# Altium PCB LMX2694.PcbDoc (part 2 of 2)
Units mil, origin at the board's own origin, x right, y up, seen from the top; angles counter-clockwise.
Board outline 2500 x 2200 mil, 4 copper layers (Top Layer, RF GND, Signal GND, Bottom Layer), stack 60.6 mil thick; 109 components, 60 nets, 306 pads, 206 vias.
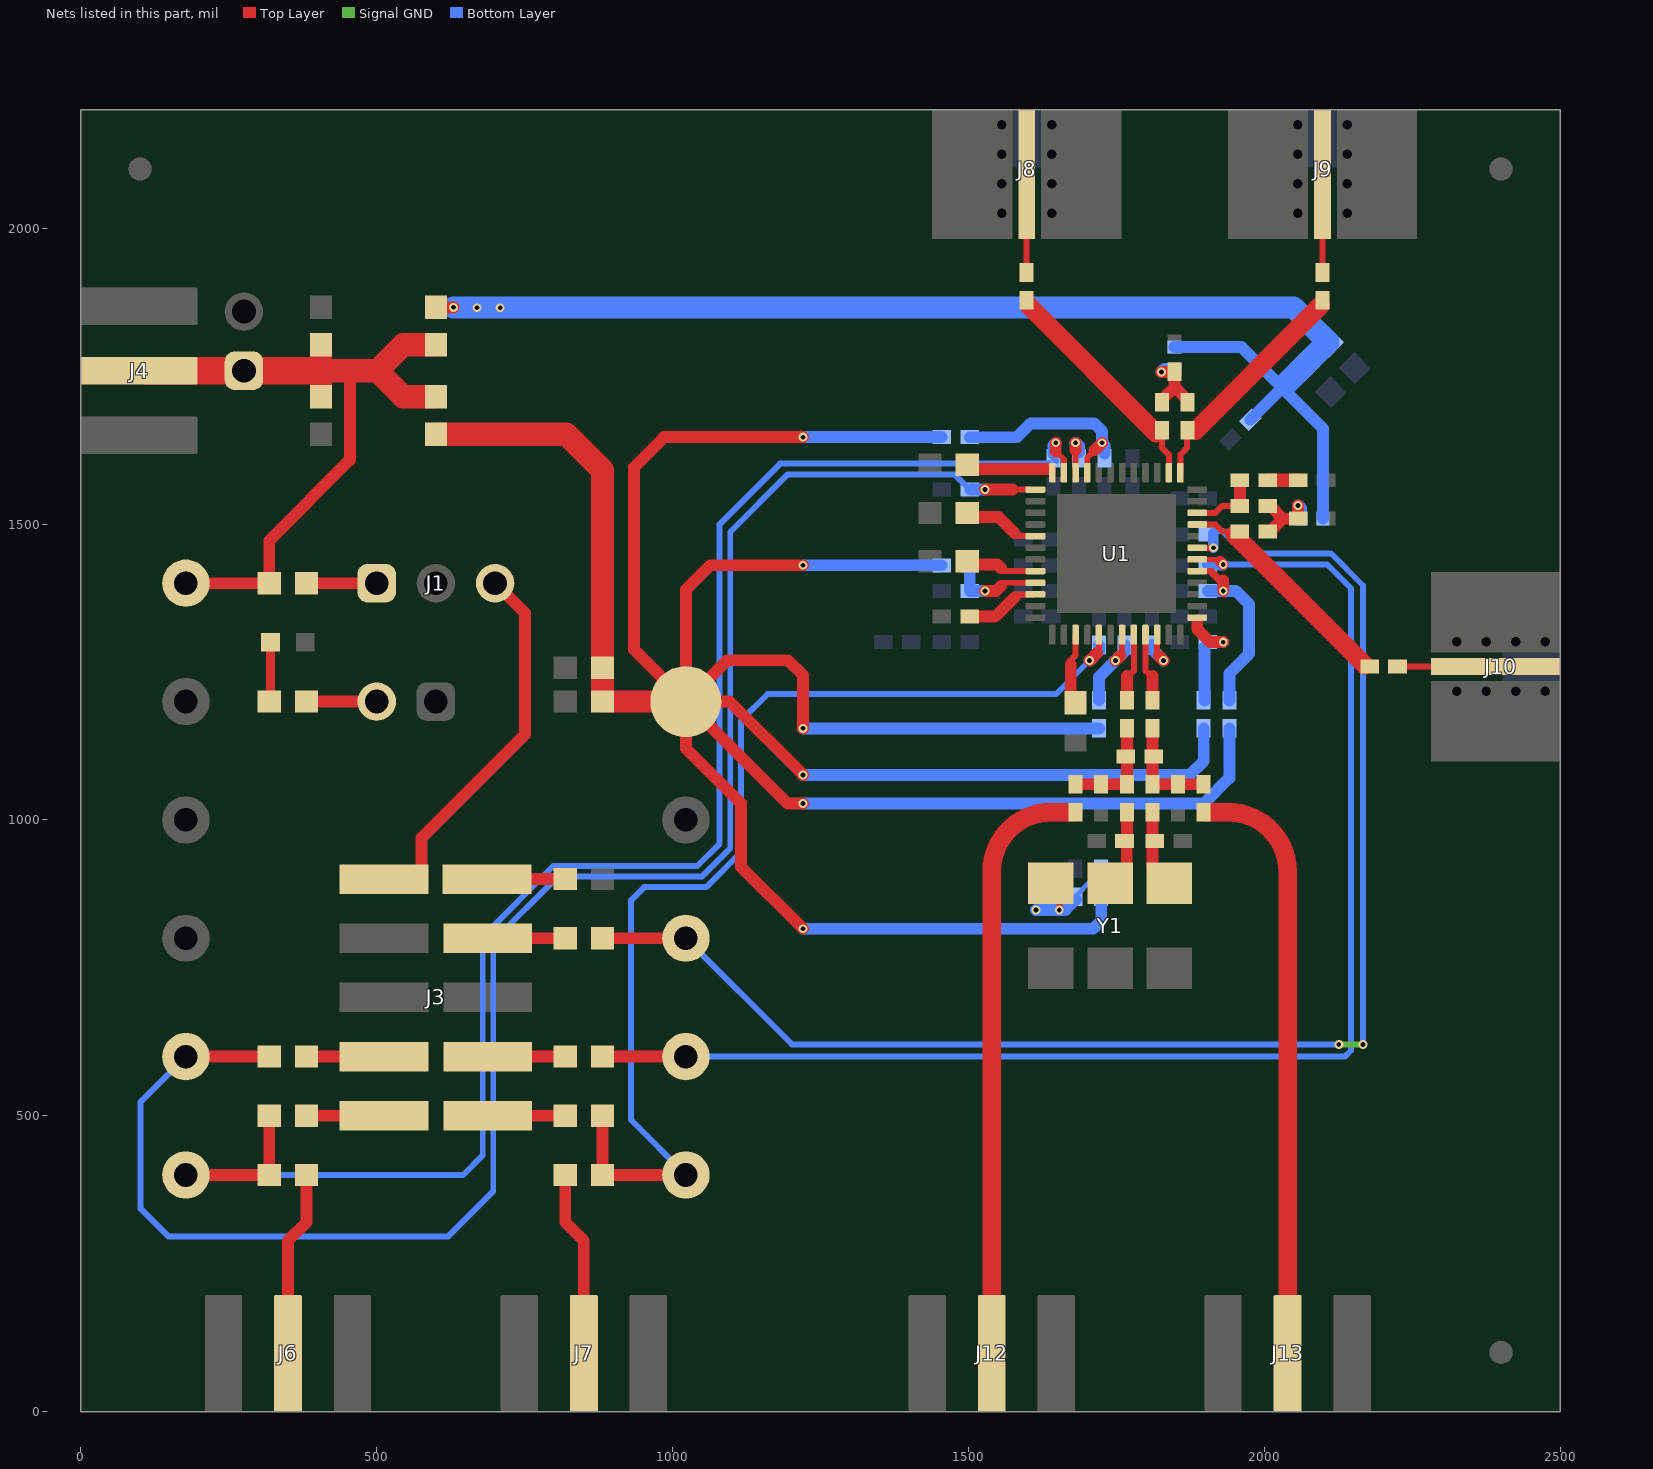
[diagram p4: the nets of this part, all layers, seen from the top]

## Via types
v1: diameter 15, hole 8, Top Layer to Bottom Layer, tented both sides, 181 vias
v2: diameter 19.68, hole 11.81, Top Layer to Bottom Layer, tented both sides, 25 vias

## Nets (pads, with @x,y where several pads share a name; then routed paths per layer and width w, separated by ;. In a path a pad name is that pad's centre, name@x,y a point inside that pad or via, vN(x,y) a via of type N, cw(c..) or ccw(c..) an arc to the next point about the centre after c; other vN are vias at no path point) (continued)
NetC14_1: C14.1 R18.2 U1.33 | length 357.2
  Top Layer w10: U1.33@1700.79,1585.83 U1.33@1700.79,1586.81 1700.79,1612.4 v1(1725.79,1637.4)
  Top Layer w20: 1713.19,1625 v1(1725.79,1637.4)
  Bottom Layer w20: R18.2@1502.36,1646.65 1581.89,1646.65 1605.32,1670.08 1712.2,1670.08 1725.79,1656.5 v1(1725.79,1637.4) 1730.12,1633.07 C14.1@1730.12,1619.49
NetC15_1: C15.1 R17.2 U1.45 | length 171.7
  Top Layer w10: 1550,1387.2 1556.89,1400 ; 1554.92,1400.79 U1.45@1613.19,1400.79 ; 1555.51,1395.67 1560.43,1399.61
  Top Layer w20: v1(1528.15,1387.01) 1545.87,1387.01 ; 1546.85,1387.01 1555.51,1395.67
  Bottom Layer w20: C15.1@1502.17,1387.01 v1@1528.35,1387.01 ; C15.1@1502.17,1393.9 R17.2@1502.17,1430.32
NetC16_1: C16.1 R16.2 U1.17 | length 329.7
  Top Layer w10: U1.17@1886.81,1420.13 U1.17@1886.81,1420.47 1909.25,1420.47
  Top Layer w12: 1910.43,1419.29 1930.71,1399.02 1934.45,1395.28
  Top Layer w20: v1(1930.71,1387.01) 1930.71,1399.02 1930.71,1404.53
  Bottom Layer w20: C16.1@1904.53,1387.01 v1(1930.71,1387.01) 1951.57,1387.01 1974.41,1364.17 1974.41,1280.71 1940.94,1247.24 R16.2@1940.94,1201.97
NetC17_1: C17.1 R15.2 U1.13 | length 183.6
  Top Layer w20: U1.13@1886.81,1337.01 1886.81,1322.05 1908.46,1300.39 v1(1930.71,1300.39)
  Bottom Layer w20: R15.2@1899.02,1201.97 C17.1@1899.02,1291.73 ; C17.1@1904.72,1300.39 v1(1930.71,1300.39)
NetC18_1: C18.1 R14.2 U1.7 | length 155.1
  Top Layer w10: 1759.84,1280.51 U1.7@1759.84,1313.19
  Top Layer w20: v1@1748.43,1269.09 1756.3,1276.97
  Bottom Layer w20: R14.2@1720.47,1202.17 1720.47,1241.34 v1(1748.43,1269.29) 1763.78,1284.65 C18.1@1763.78,1295.47
NetC19_1: C19.1 U1.10 | length 78
  Top Layer w10: 1818.9,1280.12 U1.10@1818.9,1313.19
  Top Layer w20: 1822.24,1276.77 v1(1829.72,1269.29)
  Bottom Layer w20: C19.1@1810.04,1295.47 1810.04,1288.98 v1(1829.72,1269.29)
NetC20_1: C20.1 U1.46 | length 113
  Top Layer w10: 1576.57,1381.1 U1.46@1611.02,1381.1
  Top Layer w20: C20.1@1510.83,1343.9 1544.09,1343.9 ; 1546.06,1344.09 1578.15,1375.98
NetC21_1: C21.1 U1.44 | length 114.2
  Top Layer w10: 1554.72,1420.47 U1.44@1613.19,1420.47
  Top Layer w20: C21.1@1502.17,1432.87 1503.35,1431.69 1548.82,1431.69 1554.92,1425.59
NetC22_1: C22.1 U1.36 | length 139.6
  Top Layer w10: C22.1@1509.06,1598.23 C22.1@1509.25,1598.43 ; U1.36@1641.73,1586.81 U1.36@1641.73,1598.43
  Top Layer w20: C22.1@1509.25,1592.91 U1.36@1637.01,1592.91
NetC23_1: C23.1 U1.3 | length 107.8
  Top Layer w10: 1670.47,1267.72 1681.1,1278.35 U1.3@1681.1,1313.19 ; C23.1@1671.26,1205.71 C23.1@1672.05,1206.5 ; C23.1@1680.91,1198.43 C23.1@1681.1,1198.62
  Top Layer w20: C23.1@1672.83,1206.5 1672.83,1262.99
NetC24_1: C24.1 U1.34 | length 70.1
  Top Layer w10: U1.34@1681.1,1586.81 1681.1,1625.59
  Top Layer w20: 1681.1,1625.39 v1(1681.1,1637.4)
  Bottom Layer w20: v1(1681.1,1637.4) 1686.81,1631.69 C24.1@1686.81,1620.47
NetC25_1: C25.1 U1.41 | length 136.6
  Top Layer w10: 1573.23,1489.96 1583.66,1479.53 ; 1579.13,1479.53 U1.41@1613.39,1479.53
  Top Layer w20: C25.1@1502.56,1511.02 1503.54,1512.01 1550.59,1512.01 1578.35,1484.45
NetC26_2: C26.2 L1.2 R19.2 R20.2 | length 141.7
  Top Layer w10: R19.2@1826.77,1705.91 R19.2@1826.77,1709.84 ; R20.2@1869.88,1705.91 R20.2@1869.88,1710.04
  Top Layer w15: C26.2@1848.43,1757.09 C26.2@1848.82,1757.09
  Top Layer w20: v1(1826.18,1757.09) C26.2@1848.43,1757.09 1848.43,1731.5 ; R19.2@1826.77,1709.84 1848.43,1731.5 ; R20.2@1869.88,1710.04 1848.43,1731.5
  Bottom Layer w10: L1.2@1848.43,1762.01 L1.2@1848.62,1762.01
  Bottom Layer w20: v1(1826.18,1757.09) 1831.1,1762.01 L1.2@1848.43,1762.01
NetC27_1: C27.1 J8.1 | length 169.7
  Top Layer w10: C27.1@1598.43,1925.2 J8.1@1598.43,2091 J8.1@1598.43,2094.88
NetC27_2: C27.2 R19.1 U1.26 | length 381.9
  Top Layer w10: R19.1@1826.77,1658.66 1826.77,1629.13 1838.58,1617.32 U1.26@1838.58,1586.81
  Top Layer w31.5: C27.2@1601.77,1869.29 R19.1@1817.52,1653.54
NetC28_1: C28.1 J9.1 | length 171.2
  Top Layer w10: J9.1@2097.64,2096.06 2098.43,2095.28 J9.1@2098.43,2091 C28.1@2098.43,1925.2
NetC28_2: C28.2 R20.1 U1.25 | length 376
  Top Layer w10: U1.25@1858.27,1586.81 1858.27,1617.32 1869.68,1628.74 R20.1@1869.68,1658.66
  Top Layer w31.5: 1883.66,1657.87 C28.2@2095.47,1869.49
NetC29_2: C29.2 L2.2 R21.2 R22.2 | length 141.2
  Top Layer w10: R22.2@2005.91,1487.4 R22.2@2009.84,1487.4 ; R21.2@2005.91,1530.71 R21.2@2009.84,1530.71
  Top Layer w20: R22.2@2009.84,1487.4 2031.5,1509.06 ; R21.2@2009.84,1530.71 2031.5,1509.06 ; v1(2057.09,1531.3) C29.2@2057.09,1509.06 2031.5,1509.06
  Bottom Layer w20: v1(2057.09,1531.3) 2062.01,1526.38 L2.2@2062.01,1509.06
NetC30_1: C30.1 R33.2 | length 52.5
  Top Layer w12: C30.1@2004.92,1573.23 2005.71,1574.02 C30.1@2005.91,1574.02
  Top Layer w23.62: C30.1@2005.91,1574.02 R33.2@2057.09,1574.02
NetC30_2: C30.2 R21.1 U1.22 | length 120.9
  Top Layer w10: U1.22@1886.81,1518.9 1917.32,1518.9 1929.13,1530.71 R21.1@1958.66,1530.71
  Top Layer w10.24: R21.1@1958.66,1530.71 1958.66,1530.12 R21.1@1958.86,1529.92
  Top Layer w20: R21.1@1958.66,1530.71 C30.2@1958.66,1574.02
NetC31_1: C31.1 J10.1 | length 165.8
  Top Layer w10.24: C31.1@2225.2,1259.06 J10.1@2391,1259.06
NetC31_2: C31.2 R22.1 U1.21 | length 387.4
  Top Layer w10: U1.21@1886.81,1499.21 1917.32,1499.21 1929.13,1487.4 R22.1@1958.66,1487.4
  Top Layer w31.5: R22.1@1950.2,1481.5 C31.2@2169.88,1261.81
NetC32_1: C32.1 U1.8 | length 119.3
  Top Layer w10: 1767.52,1240.16 1767.72,1240.16 1779.53,1251.97 U1.8@1779.53,1313.19
  Top Layer w20: C32.1@1767.72,1201.97 1767.72,1243.11
NetC32_2: C32.2 R23.2 R25.2 R29.2 R31.1 | length 165.9
  Top Layer w20: R31.1@1681.1,1060.24 1723.62,1060.24 R29.2@1724.41,1060.24 R25.2@1767.72,1060.24 R23.2@1767.72,1100.59 ; R23.2@1767.72,1115.75 C32.2@1767.72,1154.72
NetC33_1: C33.1 U1.9 | length 121.9
  Top Layer w10: U1.9@1799.21,1313.19 1799.21,1251.97 1811.61,1239.57 1811.61,1237.6
  Top Layer w20: C33.1@1811.02,1201.97 1811.02,1243.11
NetC33_2: C33.2 R23.1 R28.1 R30.2 R32.1 | length 153.9
  Top Layer w20: R23.1@1811.02,1097.83 R28.1@1811.02,1060.24 R30.2@1854.33,1060.24 ; R23.1@1811.02,1115.94 C33.2@1811.02,1154.72 ; R30.2@1863.39,1060.24 R32.1@1897.64,1060.24
NetC34_1: C34.1 R24.2 Y1.6 | length 185.6
  Top Layer w10: v1(1653.54,847.83) 1653.54,892.13 Y1.6@1654.72,893.31
  Bottom Layer w8: C34.1@1681.1,870.08 R24.2@1724.41,917.32
  Bottom Layer w10: v1@1653.35,847.83 v1@1653.94,848.43
  Bottom Layer w20: v1(1614.17,847.83) v1@1653.35,847.83 ; v1(1653.54,847.83) 1663.78,847.83 C34.1@1681.69,865.75
NetD1_1: D1.1 R8.2 | length 100.4
  Top Layer w15: R8.2@319.09,1200.2 320.47,1201.57 D1.1@320.47,1300
NetJ1_1: J1.1 R7.1 | length 119.2
  Top Layer w20: R7.1@381.5,1401.57 383.07,1400 J1.1@500,1400
NetJ1_3: J1.3 J3.1 | length 596
  Top Layer w20: J3.1@575.59,897.44 575.59,969.29 750.39,1144.09 750.39,1349.8 J1.3@700,1400.2
NetJ2_2: J2.2 R8.1 | length 117.7
  Top Layer w20: R8.1@382.28,1200 J2.2@500,1200
NetJ3_2: J3.2 R6.1 | length 133.5
  Top Layer w10: R6.1@818.5,900 R6.1@820,900
  Top Layer w20: J3.2@686.5,900 R6.1@818.5,900
NetJ3_4: J3.4 R5.1 | length 132.5
  Top Layer w10: R5.1@818.5,800 R5.1@820,800
  Top Layer w20: J3.4@687.5,800 R5.1@818.5,800
NetJ3_7: J3.7 R1.2 | length 127.5
  Top Layer w20: R1.2@385,600 J3.7@512.5,600
NetJ3_8: J3.8 R4.1 | length 134.6
  Top Layer w10: R4.1@815,600 R4.1@820,595
  Top Layer w20: J3.8@687.5,600 R4.1@815,600
NetJ3_9: J3.9 R2.1 | length 128.5
  Top Layer w20: R2.1@381.5,500 J3.9@510,500
NetJ3_10: J3.10 R3.1 | length 132.5
  Top Layer w10: R3.1@818.5,500 R3.1@820,500
  Top Layer w20: J3.10@687.5,500 R3.1@818.5,500
NetJ6_1: J6.1 R11.1 | length 319.7
  Top Layer w20: J6.1@350,93.31 J6.1@350,98.33 350,288.58 381.5,320.08 R11.1@381.5,400
NetJ7_1: J7.1 R12.1 | length 321.7
  Top Layer w20: R12.1@818.5,400 818.5,320.08 850,288.58 J7.1@850,98.33 850,94.09 J7.1@848.03,92.13
NetJ12_1: J12.1 R31.2 | length 999.6
  Top Layer w10: J12.1@1539.37,107.87 J12.1@1539.37,110
  Top Layer w31.5: J12.1@1539.37,110 1539.37,912.99 cw(c1639.37,912.99) 1639.37,1012.99 R31.2@1676.77,1012.99
NetJ13_1: J13.1 R32.2 | length 998
  Top Layer w10: J13.1@2039.37,109.45 J13.1@2039.37,110
  Top Layer w31.5: R32.2@1901.97,1012.99 1939.37,1012.99 cw(c1939.37,912.99) 2039.37,912.99 J13.1@2039.37,110
NetR25_1: R25.1 R26.1 Y1.5 | length 97.2
  Top Layer w20: Y1.5@1737.4,893.31 Y1.5@1739.37,893.31 ; R26.1@1763.78,964.57 1767.52,960.83 Y1.5@1767.52,919.29 ; R26.1@1767.72,964.57 R25.1@1767.72,1012.99
NetR27_1: R27.1 R28.2 Y1.4 | length 87.9
  Top Layer w20: R27.1@1810.83,971.85 1811.02,972.05 R28.2@1811.02,1012.99 ; Y1.4@1811.02,919.49 1811.02,960.63 R27.1@1814.96,964.57
RECAL_EN: C1.1 R1.1 TP5.1 U1.37 | length 3053.6
  Top Layer w10: 1574.8,1558.27 U1.37@1604.33,1558.27
  Top Layer w20: TP5.1@180,600 R1.1@318.5,600 ; v1(1528.15,1558.27) 1574.8,1558.27
  Bottom Layer w10: TP5.1@177.5,600 100.55,523.05 100.55,343.62 147.95,296.22 620.83,296.22 697.01,372.4 697.01,795.35 805.83,904.17 1049.25,904.17 1097.44,952.36 1097.44,1486.61 1194.88,1584.06 1476.18,1584.06 C1.1@1501.97,1558.27
  Bottom Layer w20: C1.1@1503.35,1558.27 v1(1528.15,1558.27)
SCK: C4.1 R4.2 TP8.1 U1.18 | length 2342.1
  Top Layer w8: U1.18@1886.81,1440.16 1922.05,1440.16 ; v1@1930.73,1432.66 v1@1930.91,1432.48
  Top Layer w18: 1924.8,1437.4 v1(1930.71,1431.5)
  Top Layer w20: R4.2@881.5,600 TP8.1@1020,600
  Bottom Layer w10: TP8.1@1022.44,600 TP8.1@1022.5,600 ; TP8.1@1030,600 2136.02,600 2146.46,610.43 2146.46,1391.34 2106.3,1431.5 v1(1930.71,1431.5)
  Bottom Layer w20: C4.1@1905.12,1431.5 v1(1930.71,1431.5)
SDI: C5.1 R5.2 TP4.1 U1.19 | length 2475.2
  Top Layer w10: U1.19@1886.81,1459.84 v1@1912.8,1459.84
  Top Layer w20: R5.2@881.5,800 TP4.1@1020,800
  Signal GND w10: v1(2125.98,620.47) v1(2166.93,620.47)
  Bottom Layer w10: TP4.1@1022.5,800 1202.03,620.47 v1(2125.98,620.47) ; C5.1@1913.39,1488.58 1929.13,1488.58 1967.36,1450.35 2112.72,1450.35 2166.93,1396.14 v1(2166.93,620.47)
  Bottom Layer w18: v1(1913.98,1459.84) C5.1@1913.98,1484.25
SYNC: C3.1 R3.2 R12.2 TP7.1 U1.5 | length 1901.2
  Top Layer w10: R12.2@880,400 R12.2@881.5,401.5 ; TP7.1@1020,400 TP7.1@1025,395 ; 1720.47,1285.04 U1.5@1720.47,1313.19
  Top Layer w20: R12.2@881.5,400 TP7.1@1020,400 ; R12.2@881.5,401.5 R3.2@881.5,500 ; v1(1704.72,1269.29) 1717.52,1282.09
  Bottom Layer w10: TP7.1@1023.03,399.61 929.92,492.72 929.92,864.37 951.85,886.3 1056.66,886.3 1115.31,944.96 1115.31,1167.48 1160.43,1212.6 1648.03,1212.6 v1(1704.72,1269.29)
  Bottom Layer w20: v1(1704.72,1269.29) 1720.47,1285.04 C3.1@1720.47,1295.28
SYSREFREQ: C2.1 R2.2 R11.2 TP6.1 U1.35 | length 2813.5
  Top Layer w10: R11.2@318.5,401.5 R11.2@320,400 ; 1647.44,1623.03 1647.64,1622.83 1661.42,1609.06 U1.35@1661.42,1586.81
  Top Layer w20: TP6.1@180,400 R11.2@318.5,400 ; R11.2@318.5,401.5 R2.2@318.5,500 ; 1647.64,1622.05 1647.64,1622.83 v1(1647.64,1637.4)
  Bottom Layer w10: TP6.1@177.5,400 646.06,400 679.13,433.07 679.13,802.76 798.43,922.05 1041.73,922.05 1079.57,959.88 1079.57,1499.65 1181.89,1601.97 C2.1@1636.81,1601.97 ; C2.1@1643.5,1611.22 1647.83,1606.89 C2.1@1647.83,1606.1
  Bottom Layer w20: C2.1@1643.5,1618.9 1643.5,1633.27 v1(1647.64,1637.4)
VCC: C9.1 C10.1 pad.1 R9.2 R14.1 R15.1 R16.1 R17.1 R18.1 R24.1 | length 6366.8
  Top Layer w20: v1(1220.47,816.14) 1115.55,921.06 1115.55,1027.95 1022.5,1121 pad.1@1022.5,1200 ; v1(1220.47,1027.56) 1194.94,1027.56 pad.1@1022.5,1200 ; v1(1220.47,1075.98) 1096.46,1200 pad.1@1022.5,1200 ; v1(1220.47,1154.72) 1220.47,1244.09 1194.88,1269.68 1092.18,1269.68 pad.1@1022.5,1200 ; v1(1220.47,1430.32) 1063.58,1430.32 1022.5,1389.23 pad.1@1022.5,1200 ; v1(1220.47,1646.85) 985.63,1646.85 934.84,1596.06 934.84,1287.66 pad.1@1022.5,1200
  Top Layer w37.4: C9.1@881.89,1200 pad.1@1022.5,1200
  Top Layer w39.37: R9.2@602.36,1651.97 820.67,1651.97 881.5,1591.14 C10.1@881.5,1257.09 C9.1@881.5,1206.69
  Bottom Layer w20: v1(1220.47,816.14) 1710.83,816.14 1724.41,829.72 R24.1@1724.41,870.08 ; v1(1220.47,1027.56) 1897.44,1027.56 1940.94,1071.06 R16.1@1940.94,1154.72 ; v1(1220.47,1075.98) 1874.21,1075.98 1897.64,1099.41 R15.1@1897.64,1154.72 ; v1(1220.47,1154.72) R14.1@1720.47,1154.72 ; v1(1220.47,1430.32) R17.1@1454.72,1430.32 ; v1(1220.47,1646.85) R18.1@1454.72,1646.85
VCCRF: C11.1 C12.1 L1.1 L2.1 R10.2 R13.1 | length 2169.7
  Top Layer w20: R10.2@600,1866.14 v1(629.92,1866.14)
  Bottom Layer w20: L1.1@1848.43,1799.41 1961.42,1799.41 2030.41,1730.41 ; R13.1@1976.35,1676.35 2030.41,1730.41 ; C11.1@2067.52,1767.52 2067.72,1767.72 C11.1@2067.91,1767.72 ; L2.1@2099.41,1509.06 2099.41,1661.42 2030.41,1730.41
  Bottom Layer w37.4: v1(629.92,1866.14) 2049.61,1866.14 C12.1@2107.87,1807.87
  Bottom Layer w39.37: 2036.02,1736.02 C11.1@2067.52,1767.52 ; C11.1@2067.72,1767.72 C12.1@2107.09,1807.09
  other v1: 669.29,1865.55 708.66,1865.55
VDD: C7.1 C8.1 J4.1 J5.1 R7.2 R9.1 R10.1 TP10.1 | length 1268.6
  Top Layer w20: TP10.1@177.5,1400 R7.2@317.91,1400 ; R7.2@318.5,1399.02 318.5,1472.05 454.72,1608.27 454.72,1758.86 ; C8.1@404.33,1803.74 C8.1@405.71,1802.36
  Top Layer w37.4: C7.1@405.71,1714.96 405.71,1759.06 C8.1@405.71,1802.36
  Top Layer w39.37: 405.71,1759.06 500.79,1759.06 ; R9.1@598.43,1714.96 544.88,1714.96 500.79,1759.06 ; R10.1@598.43,1803.15 544.88,1803.15 500.79,1759.06
  Top Layer w47.24: J4.1@110.04,1759.06 J5.1@275.59,1759.06 405.71,1759.06
pads on no net: FID1.1 FID2.1 FID3.1 FID4.1 FID5.1 FID6.1 J3.5 SH-J1.0 SH-J2.0 U1.11 U1.12 U1.20 U1.30 U1.31 U1.38 U1.39 Y1.1 Y1.2

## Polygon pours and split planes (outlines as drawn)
GND on Top Layer "TOP_LAYER_GND_P018" (solid, remove dead copper, pour order 18): 25,1978.74 25,1884.25 196.85,1884.25 196.85,1978.74
NetC30_2 on Top Layer "TOP_LAYER_NETC30_2_P022" (solid, pour order 22): 1912.99,1521.65 1933.86,1542.52 1964.17,1542.52 1964.17,1518.9 1912.99,1518.9
NetC31_2 on Top Layer "TOP_LAYER_NETC31_2_P032" (solid, pour order 32): 1942.13,1467.32 1961.81,1467.32 1961.81,1499.21 1910.24,1499.21
NetC31_1 on Top Layer "TOP_LAYER_NETC31_1_P038" (solid, remove dead copper, pour order 38): 2287.4,1273.23 2209.45,1273.23 2209.45,1244.88 2287.4,1244.88
no net on Top Layer "TOP_LAYER_NONET_P054" (solid, remove dead copper, pour order 54): 2193.7,1273.23
NetC31_2 on Top Layer "TOP_LAYER_NETC31_2_P056" (solid, remove dead copper, pour order 56): 2157.48,1251.97 2157.48,1273.23 2193.7,1273.23 2193.7,1244.88 2164.57,1244.88
NetC28_2 on Top Layer "TOP_LAYER_NETC28_2_P058" (solid, remove dead copper, pour order 58): 1870.87,1622.83 1896.46,1648.43 1858.27,1648.43 1858.27,1622.83
NetC28_1 on Top Layer "TOP_LAYER_NETC28_1_P060" (solid, remove dead copper, pour order 60): 2084.25,1984.25 2084.25,1909.45 2112.6,1909.45 2112.6,1984.25
NetC28_2 on Top Layer "TOP_LAYER_NETC28_2_P062" (solid, remove dead copper, pour order 62): 2112.6,1893.7 2112.6,1864.57 2105.51,1857.48 2090.55,1857.48 2075.89,1872.15 2084.25,1880.51 2084.25,1893.7
NetC27_1 on Top Layer "TOP_LAYER_NETC27_1_P064" (solid, remove dead copper, pour order 64): 1584.25,1984.25 1584.25,1909.45 1612.6,1909.45 1612.6,1984.25
NetC27_2 on Top Layer "TOP_LAYER_NETC27_2_P066" (solid, remove dead copper, pour order 66): 1827.17,1621.65 1796.85,1651.97 1796.85,1656.69 1797.05,1656.89 1838.58,1656.89 1838.58,1621.65
NetC27_2 on Top Layer "TOP_LAYER_NETC27_2_P068" (solid, remove dead copper, pour order 68): 1584.25,1893.7 1584.25,1864.57 1601.57,1847.24 1601.57,1873.43 1611.61,1873.43 1612.6,1872.44 1612.6,1893.7
no net on Top Layer "TOP_LAYER_NONET_P072" (solid, remove dead copper, pour order 72): 1813.58,1249.61
no net on Top Layer "TOP_LAYER_NONET_P076" (solid, remove dead copper, pour order 76): 1600.79,625.98
no net on Top Layer "TOP_LAYER_NONET_P080" (solid, remove dead copper, pour order 80): 2183.86,1683.27
GND on Top Layer "TOP_LAYER_GND_P084" (solid, remove dead copper, pour order 84): 1875.98,716.14 1877.95,716.14 1877.95,693.9 1800.79,693.9 1800.79,716.14
GND on Top Layer "TOP_LAYER_GND_P102" (solid, remove dead copper, pour order 102): 2283.46,1234.65 2209.45,1234.65 2209.45,1195.28 2283.46,1195.28
GND on Top Layer "TOP_LAYER_GND_P108" (solid, remove dead copper, pour order 108): 1622.83,1987.2 1622.83,1909.45 1637.99,1909.45 1662.2,1933.66 1662.2,1987.2
GND on Top Layer "TOP_LAYER_GND_P112" (solid, remove dead copper, pour order 112): 1534.65,1983.46 1534.65,1909.45 1574.02,1909.45 1574.02,1983.46
GND on Top Layer "TOP_LAYER_GND_P114" (solid, remove dead copper, pour order 114): 2122.83,1983.46 2122.83,1909.45 2162.2,1909.45 2162.2,1983.46
GND on Top Layer "TOP_LAYER_GND_P116" (solid, remove dead copper, pour order 116): 2284.65,1283.46 2209.45,1283.46 2209.45,1298.62 2233.66,1322.83 2284.65,1322.83
GND on Top Layer "TOP_LAYER_GND_P118" (solid, remove dead copper, pour order 118): 2073.62,1984.65 2073.62,1909.45 2058.46,1909.45 2034.25,1933.66 2034.25,1984.65
NetC4LF_1 on Top Layer "TOP_LAYER_NETC4LF_1_P120" (solid, remove dead copper, pour order 120): 1585.24,1452.17 1594.29,1443.11 1585.24,1443.11
NetC25_1 on Top Layer "TOP_LAYER_NETC25_1_P122" (solid, remove dead copper, pour order 122): 1584.65,1491.93 1593.7,1482.87 1584.65,1482.87
NetC21_1 on Top Layer "TOP_LAYER_NETC21_1_P124" (solid, remove dead copper, pour order 124): 1561.49,1433 1570.55,1423.94 1561.49,1423.94
NetC32_1 on Top Layer "TOP_LAYER_NETC32_1_P134" (solid, remove dead copper, pour order 134): 1760.83,1250.2 1776.97,1266.34 1777.36,1266.34 1777.36,1250.2
NetC33_1 on Top Layer "TOP_LAYER_NETC33_1_P136" (solid, remove dead copper, pour order 136): 1818.11,1250 1803.54,1264.57 1802.76,1264.57 1802.76,1250
GND on Top Layer "TOP_LAYER_GND_P140" (solid, remove dead copper, pour order 140): 196.85,1633.86 25,1633.86 25,1539.37 196.85,1539.37
VCCRF on Top Layer "TOP_LAYER_VCCRF_P142" (solid, remove dead copper, pour order 142): 617.72,1885.83 724.41,1885.83 724.41,1846.46 617.72,1846.46
NetC15_1 on Top Layer "TOP_LAYER_NETC15_1_P144" (solid, remove dead copper, pour order 144): 1561.81,1387.99 1570.87,1397.05 1570.87,1397.44 1561.81,1397.44
NetC20_1 on Top Layer "TOP_LAYER_NETC20_1_P146" (solid, remove dead copper, pour order 146): 1580.32,1364.27 1580.51,1364.27 1594.88,1378.64 1580.32,1378.64
NetC23_1 on Top Layer "TOP_LAYER_NETC23_1_P150" (solid, remove dead copper, pour order 150): 1682.68,1262.99 1682.68,1275.59 1676.77,1275.59 1675.98,1274.8 1675.98,1262.99
NetC34_1 on Top Layer "TOP_LAYER_NETC34_1_P152" (solid, remove dead copper, pour order 152): 1600.79,859.06 1600.79,837.99 1677.95,837.99 1677.95,859.06
GND on Top Layer "TOP_LAYER_GND_P161" (solid, pour order 161): 130.32,25 217.72,25 217.72,196.85 130.32,196.85
GND on Top Layer "TOP_LAYER_GND_P163" (solid, pour order 163): 483.46,25 569.68,25 569.68,196.85 483.46,196.85
GND on Top Layer "TOP_LAYER_GND_P165" (solid, pour order 165): 630.32,25 717.32,25 717.32,196.85 630.32,196.85
GND on Top Layer "TOP_LAYER_GND_P167" (solid, pour order 167): 983.46,25 1069.68,25 1069.68,196.85 983.46,196.85
NetC30_2 on Top Layer "TOP_LAYER_NETC30_2_P169" (solid, remove dead copper, pour order 169): 1942.91,1564.37 1942.91,1540.55 1974.41,1540.55 1974.41,1564.37
no net on Bottom Layer "BOTTOM_LAYER_NONET_P086" (solid, remove dead copper, pour order 86): 1876.97,1576.18
NetC13_1 on Bottom Layer "BOTTOM_LAYER_NETC13_1_P088" (solid, pour order 88): 1887.99,1553.94 1876.97,1564.96 1876.97,1578.15 1896.65,1578.15 1896.65,1565.55 1908.27,1553.94
SDI on Bottom Layer "BOTTOM_LAYER_SDI_P090" (solid, pour order 90): 1920.28,1471.06 1921.46,1469.88 1921.46,1459.84 1906.5,1459.84 1906.5,1471.06
GND on Bottom Layer "BOTTOM_LAYER_GND_P154" (solid, remove dead copper, pour order 154): 0.28,2200 2500.28,2200 2500.28,0 0.28,0
GND on Signal GND "SIGNAL_GND_GND_P156" (solid, remove dead copper, pour order 156): 0,2200 2500,2200 2500,0 0,0
no net on Top Overlay "NONET_L-01_P-001" (solid): 1596.46,1296.46 1612.2,1296.46 1596.46,1312.2
NetC27_2 on Top Solder "NONET_L-01_P-001" (solid): 1616.34,1877.76 1616.34,1856.3 1591.54,1856.3 1809.05,1638.78 1809.05,1685.04
no net on Top Solder "NONET_L-01_P-001" (solid): 2080.71,1877.95 2080.71,1856.3 2105.32,1856.3 1887.8,1638.78 1887.8,1685.04
no net on Top Solder "NONET_L-01_P-001" (solid, remove dead copper): 2079.72,1753.94
no net on Top Solder "NONET_L-01_P-001" (solid): 1883.86,1636.81 1857.28,1636.81 1857.28,1624.02 1852.36,1619.09 1852.36,1611.42 1864.17,1611.42 1864.17,1615.16 1883.86,1634.84
no net on Top Solder "NONET_L-01_P-001" (solid): 1839.57,1636.81 1812.99,1636.81 1812.99,1634.84 1832.68,1615.16 1832.68,1611.42 1844.49,1611.42 1844.49,1619.09 1839.57,1624.02
no net on Top Solder "NONET_L-01_P-001" (solid): 2156.3,1276.77 2156.3,1252.17 1938.78,1469.68 1985.24,1469.68 2178.15,1276.77
no net on Top Solder "NONET_L-01_P-001" (solid): 1980.32,1468.9 1986.02,1468.9 1980.32,1474.61
no net on Top Solder "NONET_L-01_P-001" (solid): 1937.01,1544.49 1937.01,1517.91 1924.41,1517.91 1919.49,1512.99 1911.42,1512.99 1911.42,1524.8 1915.16,1524.8 1934.84,1544.49
no net on Top Solder "NONET_L-01_P-001" (solid): 1937.01,1473.62 1934.84,1473.62 1915.16,1493.31 1911.42,1493.31 1911.42,1505.12 1919.49,1505.12 1924.41,1500.2 1937.01,1500.2
no net on Top Solder "NONET_L-01_P-001" (solid): 1888.58,1680.31 1888.58,1685.83 1883.07,1680.31
no net on Top Solder "NONET_L-01_P-001" (solid): 1808.27,1680.31 1808.27,1685.83 1813.78,1680.31
no net on Top Solder "NONET_L-01_P-001" (solid): 2275.98,1323.82 2233.46,1323.82 2208.46,1298.82 2208.46,1282.48 2275.98,1282.48
no net on Top Solder "NONET_L-01_P-001" (solid): 2275.98,1274.21 2246.85,1274.21 2246.85,1243.9 2275.98,1243.9
no net on Top Solder "NONET_L-01_P-001" (solid): 2275.98,1235.63 2208.46,1235.63 2208.46,1194.29 2275.98,1194.29
no net on Top Solder "NONET_L-01_P-001" (solid): 2121.85,1975.98 2121.85,1908.46 2163.19,1908.46 2163.19,1975.98
no net on Top Solder "NONET_L-01_P-001" (solid): 2113.58,1975.98 2113.58,1946.85 2083.27,1946.85 2083.27,1975.98
no net on Top Solder "NONET_L-01_P-001" (solid): 2074.61,1975.98 2033.27,1975.98 2033.27,1933.46 2058.27,1908.46 2074.61,1908.46
no net on Top Solder "NONET_L-01_P-001" (solid): 1663.19,1975.98 1663.19,1933.46 1662.99,1933.46 1637.99,1908.46 1621.85,1908.46 1621.85,1975.98
no net on Top Solder "NONET_L-01_P-001" (solid): 1613.58,1975.98 1613.58,1946.85 1583.27,1946.85 1583.27,1975.98
no net on Top Solder "NONET_L-01_P-001" (solid): 1575,1975.98 1575,1908.46 1533.66,1908.46 1533.66,1975.98
no net on Top Solder "TOP_LAYER_VDD_P128" (solid, pour order 128): 0,1978.74 196.85,1978.74 196.85,1903.54 0,1903.54
no net on Top Solder "TOP_LAYER_VDD_P128" (solid): 0,1614.57 196.85,1614.57 196.85,1539.37 0,1539.37
no net on Top Solder "TOP_LAYER_NONET_P-001" (solid): 494.49,0 569.68,0 569.68,196.85 494.49,196.85
no net on Top Solder "TOP_LAYER_NONET_P-001" (solid): 130.32,0 205.51,0 205.51,196.85 130.32,196.85
no net on Top Solder "TOP_LAYER_NONET_P-001" (solid): 630.32,0 705.51,0 705.51,196.85 630.32,196.85
no net on Top Solder "TOP_LAYER_NONET_P-001" (solid): 994.49,0 1069.68,0 1069.68,196.85 994.49,196.85
no net on Top Solder "TOP_LAYER_NONET_P-001" (solid): 1940.94,1556.3 1976.38,1556.3 1976.38,1548.43 1940.94,1548.43
GND on RF GND "RF_GND_GND_P158" (solid, remove dead copper, pour order 158): 0,0 2500,0 2500,2200 0,2200
no net on RF GND "RF_GND_NONET_P160" (solid, remove dead copper, pour order 160): 400,0
no net on Bottom Solder "TOP_LAYER_VDD_P128" (solid): 0,1614.57 196.85,1614.57 196.85,1539.37 0,1539.37
no net on Bottom Solder "TOP_LAYER_VDD_P128" (solid): 0,1978.74 196.85,1978.74 196.85,1903.54 0,1903.54
no net on Bottom Solder "NONET_L-01_P-001" (solid): 130.32,0 130.32,196.85 205.51,196.85 205.51,0
no net on Bottom Solder "NONET_L-01_P-001" (solid): 569.68,0 569.68,196.85 494.49,196.85 494.49,0
no net on Bottom Solder "TOP_LAYER_NONET_P-001" (solid): 630.32,0 705.51,0 705.51,196.85 630.32,196.85
no net on Bottom Solder "TOP_LAYER_NONET_P-001" (solid): 994.49,0 1069.68,0 1069.68,196.85 994.49,196.85

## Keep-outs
Keep-Out Layer:
  text ".Layer_Name" at -423,-1858.49 h60

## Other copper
Top Layer:
  text ".Layer_Name" at -423,-1858.49 h60
RF GND:
  text ".Layer_Name" at -423,-1858.49 h60
Signal GND:
  text ".Layer_Name" at -423,-1858.49 h60
Bottom Layer:
  text ".Layer_Name" at -423,-1858.49 h60

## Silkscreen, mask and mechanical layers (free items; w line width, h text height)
Top Overlay:
  lines w7: 1596.46,1587.8 1596.46,1603.54 1612.2,1603.54 ; 1887.8,1296.46 1903.54,1296.46 1903.54,1312.2 ; 1887.8,1603.54 1903.54,1603.54 1903.54,1587.8
  lines w10: 500,1460 500,1470 580,1470 580,1460 ; 620,1460 620,1470 700,1470 700,1460
  text "-" at 340,1850 h25
  text "+" at 340,1750 h25
  text "3.3 V" at 290,1580 h25 r90
  text "HW: CE is pulled-up by R7 / SW: CE is software configurable" at 440.16,1498.03 h25
  text "HW" at 520,1490 h25
  text "SW" at 640,1490 h25
  text ".Layer_Name" at -423,-1858.49 h60
Bottom Overlay:
  text ".Layer_Name" at -423,-1858.49 h60
Top Paste:
  text ".Layer_Name" at -423,-1858.49 h60
Bottom Paste:
  text ".Layer_Name" at -423,-1858.49 h60
Top Solder:
  text ".Layer_Name" at -423,-1858.49 h60
  text ".Layer_Name" at -423,-1858.49 h60
Bottom Solder:
  text ".Layer_Name" at -423,-1858.49 h60
Drill Guide:
  text ".Layer_Name" at -423,-1858.49 h60
M1 Board Outline:
  the board outline again, w10
  text ".Layer_Name" at -423,-1858.49 h60
M2 Board Dimensions:
  rectangle: -875,-1400 -500,-1275
  rectangle: -1000,-1275 -875,-1150
  lines w7: -1000,-1275 0,-1275 ; -875,-1400 -875,-1150 ; -750,-1400 -750,-1150 ; -500,-1400 -500,-1150 ; -250,-1400 -250,-1150 ; -1000,-1400 -1000,-1150 0,-1150 0,-1400 -1000,-1400
  text ".Layer_Name" at -423,-1858.49 h60
M3 3D STEP Top:
  text ".Layer_Name" at -423,-1858.49 h60
M4 3D STEP Bottom:
  text ".Layer_Name" at -423,-1858.49 h60
M5 Assembly Top:
  lines w10: -1292,-1930.17 5308,-1930.17 ; -1292,-1726.83 5310,-1726.83 ; -1292,-1523.5 -1292,-2133.5 2713,-2133.5 5310,-2133.5 5310,-1523.5 -1291.5,-1523.5 -1291.5,-2133.5 284,-2133.5 ; 1173,-2133.5 1173,-1523.5 ; 2440,-1726.83 2440,-1523.5 ; 3280,-1726.83 3280,-1523.5 ; 3902,-2140 3902,-1937.17
  text "COMPONENTS MARKED 'DNP' SHOULD NOT BE POPULATED." at 153.5,-1318.5 h60
  text "ASSEMBLY VARIANT:" at 153,-1434 h60
  text ".VariantName" at 1189,-1434 h60
  text "PCB VIEWED FROM TOP SIDE" at -1228.5,-1655.67 h60
  text "BOARD #:" at 1248,-1655.67 h60
  text "REV:" at 2638,-1655.67 h60
  text ".PCB_Rev" at 2929.5,-1655.67 h60
  text "SVN REV:" at 3476,-1655.67 h60
  text ".VersionControl_RevNumber" at 3982,-1655.67 h60
  text "TID #:" at 1248,-1859 h60
  text ".TID" at 1793.5,-1859 h60
  text "PLOT NAME =" at -1228.5,-2064.34 h60
  text "GENERATED    :" at 1250,-2064.34 h60
  text ".Print_Date" at 2119.5,-2064.34 h60
  text ".Print_Time" at 2848.5,-2064.34 h60
M6 Assembly Bottom:
  lines w10: -1292.5,-1727.33 5309.5,-1727.33 ; -1290.5,-1930.67 5309.5,-1930.67 ; 115.5,-2140.5 115.5,-1937.67 ; 737.5,-1727.33 737.5,-1524 ; 1577.5,-1727.33 1577.5,-1524 ; 2844.5,-2134 2844.5,-1524 ; 3733.5,-2134 5309,-2134 5309,-1524 -1292.5,-1524 -1292.5,-2134 1304.5,-2134 5309.5,-2134 5309.5,-1524
  text "COMPONENTS MARKED 'DNP' SHOULD NOT BE POPULATED." at 5102,-1318 h60
  text ".VariantName" at 4058,-1434 h60
  text "ASSEMBLY VARIANT:" at 5097,-1434 h60
  text ".VersionControl_RevNumber" at 35.5,-1656.17 h60
  text "SVN REV:" at 541.5,-1656.17 h60
  text ".PCB_Rev" at 1088,-1656.17 h60
  text "REV:" at 1379.5,-1656.17 h60
  text "BOARD #:" at 2769.5,-1656.17 h60
  text "PCB VIEWED FROM BOTTOM SIDE" at 5246,-1656.17 h60
  text ".TID" at 2224,-1859.5 h60
  text "TID #:" at 2769.5,-1859.5 h60
  text ".Print_Time" at 1169,-2064.84 h60
  text ".Print_Date" at 1898,-2064.84 h60
  text "GENERATED    :" at 2767.5,-2064.84 h60
  text "PLOT NAME =" at 5246,-2064.84 h60
M9 Title Sheet:
  lines w10: -1491.5,41.5 -1291.5,41.5 ; -1491.5,2416.5 -1291.5,2416.5 ; -1491.5,4791.5 -1291.5,4791.5 ; 1008.5,-2333.5 1008.5,-2133.5 ; 1008.5,6966.5 1008.5,7166.5 ; 3508.5,-2333.5 3508.5,-2133.5 ; 3508.5,6966.5 3508.5,7166.5 ; 5321,-2133.5 5321,-1523.5 10303.5,-1523.5 ; 6008.5,-2333.5 6008.5,-2133.5 ; 6008.5,6966.5 6008.5,7166.5 ; 8508.5,-2333.5 8508.5,-2133.5 ; 8508.5,6966.5 8508.5,7166.5 ; 10303.5,-2133.5 10303.5,-1523.5 ; 10303.5,-1823.5 13303.5,-1823.5 ; 10303.5,-1223.5 13303.5,-1223.5 ; 10304.5,-629.5 13304.5,-629.5 ; 11008.5,-2333.5 11008.5,-2133.5 ; 11008.5,6966.5 11008.5,7166.5 ; 11808.5,-2123.5 11808.5,-1523.5 ; 13303.5,-1523.5 10303.5,-1523.5 ; 13303.5,-923.5 10303.5,-923.5 ; 13308.5,-933.5 13308.5,-2133.5 ; 13308.5,-129 10304.5,-129 10303.5,-129 10303.5,-629.5 10303.5,-923.5 ; 13308.5,41.5 13508.5,41.5 ; 13308.5,2416.5 13508.5,2416.5 ; 13308.5,4791.5 13508.5,4791.5 ; 10303.5,-1523.5 10303.5,-923.5 ; 13308.5,-2133.5 -1291.5,-2133.5 -1291.5,6966.5 13308.5,6966.5 13308.5,-2133.5 ; -1491.5,-2333.5 13508.5,-2333.5 13508.5,7166.5 -1491.5,7166.5 -1491.5,-2333.5
  text "1" at -260.16,7036.5 h70
  text "2" at 2235.5,7036.5 h70
  text "3" at 4724.84,7036.5 h70
  text "4" at 7231.51,7036.5 h70
  text "5" at 9730.5,7036.5 h70
  text "6" at 12235.5,7036.5 h70
  text "A" at -1416.5,5893.5 h70
  text "A" at 13383.5,5893.5 h70
  text "B" at -1416.5,3513.5 h70
  text "B" at 13383.5,3513.5 h70
  text "C" at -1416.5,1138.5 h70
  text "C" at 13383.5,1138.5 h70
  text "PROJECT TITLE:" at 10343.5,-722.5 h45
  text "DESIGNED FOR:" at 10343.5,-1023.5 h45
  text ".PRJ_Customer" at 10393.5,-1163.5 h70
  text "D" at -1416.5,-1231.5 h70
  text "D" at 13383.5,-1231.5 h70
  text "FILE NAME:" at 10343.5,-1323.5 h45
  text "Texas Instruments (TI) and/or its licensors do not warrant the accuracy or completeness of this specification" at 5374,-1605.34 h45
  text "ENGINEER:" at 10343.5,-1613.5 h45
  text "LAYOUT BY:" at 11848.5,-1613.5 h45
  text "or any information contained therein. TI and/or its licensors do not warrant that this design will meet" at 5329.01,-1718 h45
  text "the specifications, will be suitable for your application or fit for any particular purpose, or will operate in" at 5329.01,-1830.67 h45
  text ".Layer_Name" at -423,-1858.49 h60
  text "ALTIUM DESIGNER VERSION:" at 11848.5,-1923.5 h45
  text "an implementation. TI and/or its licensors do not warrant that the design is production worthy. You should" at 5329.01,-1943.33 h45
  text "completely validate and test your design implementation to confirm the system functionality for your application." at 5374,-2056 h45
  text ".print_Scale" at 10393.5,-2056.83 h70
  text ".Application_BuildNumber" at 11899,-2056.83 h70
  text "1" at -260.16,-2263.5 h70
  text "2" at 2235.5,-2263.5 h70
  text "3" at 4724.84,-2263.5 h70
  text "4" at 7231.51,-2263.5 h70
  text "5" at 9730.5,-2263.5 h70
  text "6" at 12235.5,-2263.5 h70
M10 Fab Notes:
  text ".Layer_Name" at -423,-1858.49 h60
M11 Gerber Information:
  lines w10: -1292,-1930.17 5308,-1930.17 ; -1292,-1726.83 5310,-1726.83 ; -1292,-1523.5 -1292,-2133.5 2713,-2133.5 5310,-2133.5 5310,-1523.5 -1291.5,-1523.5 -1291.5,-2133.5 284,-2133.5 ; 1173,-2133.5 1173,-1523.5 ; 2440,-1726.83 2440,-1523.5 ; 3280,-1726.83 3280,-1523.5 ; 3902,-2140 3902,-1937.17
  text "ALL ARTWORK VIEWED FROM TOP SIDE" at -1228.5,-1655.67 h60
  text "BOARD #:" at 1248,-1655.67 h60
  text "REV:" at 2638,-1655.67 h60
  text ".PCB_Rev" at 2929.5,-1655.67 h60
  text "SVN REV:" at 3476,-1655.67 h60
  text ".VersionControl_RevNumber" at 3982,-1655.67 h60
  text "LAYER NAME =" at -1228.5,-1858.49 h60
  text "TID #:" at 1248,-1859 h60
  text ".TID" at 1793.5,-1859 h60
  text "PLOT NAME =" at -1228.5,-2064.34 h60
  text "GENERATED    :" at 1250,-2064.34 h60
  text ".Print_Date" at 2119.5,-2064.34 h60
  text ".Print_Time" at 2848.5,-2064.34 h60
M12 Stackup:
  drawing of 295 lines, arcs and shapes, not listed
  text "Layer" at 3450.09,1215 h60
  text "Name" at 3860,1215 h60
  text "Material" at 4789.74,1215 h60
  text "Thickness" at 5749.48,1215 h60
  text "Constant" at 6399.31,1215 h60
  text "Board Layer Stack" at 6969.18,1215 h60
  text "1" at 3450.09,1095 h60
  text "Top Overlay" at 3860,1095 h60
  text "2" at 3450.09,975 h60
  text "Top Solder" at 3860,975 h60
  text "Solder Resist" at 4789.74,975 h60
  text "0.40mil" at 5749.48,975 h60
  text "3.5" at 6399.31,975 h60
  text "3" at 3450.09,855 h60
  text "Top Layer" at 3860,855 h60
  text "Copper" at 4789.74,855 h60
  text "1.40mil" at 5749.48,855 h60
  text "4" at 3450.09,735 h60
  text "Dielectric1" at 3860,735 h60
  text "Rogers RO4350B" at 4789.74,735 h60
  text "16.00mil" at 5749.48,735 h60
  text "3.66" at 6399.31,735 h60
  text "5" at 3450.09,615 h60
  text "RF GND" at 3860,615 h60
  text "Copper" at 4789.74,615 h60
  text "1.40mil" at 5749.48,615 h60
  text "6" at 3450.09,495 h60
  text "Dielectric 2" at 3860,495 h60
  text "FR4" at 4789.74,495 h60
  text "23.00mil" at 5749.48,495 h60
  text "4.2" at 6399.31,495 h60
  text "7" at 3450.09,375 h60
  text "Signal GND" at 3860,375 h60
  text "Copper" at 4789.74,375 h60
  text "1.40mil" at 5749.48,375 h60
  text "8" at 3450.09,255 h60
  text "Dielectric 3" at 3860,255 h60
  text "FR4" at 4789.74,255 h60
  text "16.00mil" at 5749.48,255 h60
  text "4.2" at 6399.31,255 h60
  text "9" at 3450.09,135 h60
  text "Bottom Layer" at 3860,135 h60
  text "Copper" at 4789.74,135 h60
  text "1.40mil" at 5749.48,135 h60
  text "10" at 3450.09,15 h60
  text "Bottom Solder" at 3860,15 h60
  text "Solder Resist" at 4789.74,15 h60
  text "0.40mil" at 5749.48,15 h60
  text "3.5" at 6399.31,15 h60
  text "11" at 3450.09,-105 h60
  text "Bottom Overlay" at 3860,-105 h60
  text ".Layer_Name" at -423,-1858.49 h60
M13 Component Bodies Top:
  text ".Layer_Name" at -423,-1858.49 h60
M14 Component Bodies Bottom:
  text ".Layer_Name" at -423,-1858.49 h60
M15 Courtyards Top:
  text ".Layer_Name" at -423,-1858.49 h60
M16 Courtyards Bottom:
  text ".Layer_Name" at -423,-1858.49 h60
Drill Drawing:
  lines w10: 3450.09,2174.87 3505.34,2174.87 3477.72,2119.62 3450.09,2174.87 ; 3450.09,2243.94 3505.34,2243.94 3505.34,2299.19 3450.09,2299.19 3450.09,2243.94 ; 3450.09,2382.07 3463.9,2382.07 3477.72,2368.26 3491.53,2382.07 3505.34,2382.07 3491.53,2395.88 3505.34,2409.7 3491.53,2409.7 3477.72,2423.51 3463.9,2409.7 3450.09,2409.7 3463.9,2395.88 3450.09,2382.07 ; 3450.09,2492.58 3477.72,2506.39 3505.34,2492.58 3491.53,2520.2 3505.34,2547.83 3477.72,2534.02 3450.09,2547.83 3463.9,2520.2 3450.09,2492.58
  lines w12: 3400,2082.32 6631.49,2082.32 ; 3400,2579.6 6631.49,2579.6 ; 3737.86,1958 3737.86,2703.92 ; 4069.86,1958 4069.86,2703.92 ; 4706.43,1958 4706.43,2703.92 ; 4965.57,1958 4965.57,2703.92 ; 5340.72,1958 5340.72,2703.92 ; 6065.05,1958 6065.05,2703.92 ; 3400,1958 6631.49,1958 6631.49,2703.92 3400,2703.92 3400,1958
  text "Symbol" at 3474.59,2616.9 h72
  text "Quantity" at 3775.16,2616.9 h72
  text "Finished Hole Size" at 4107.16,2616.9 h72
  text "Plated" at 4743.72,2616.9 h72
  text "Hole Type" at 5002.86,2616.9 h72
  text "Drill Layer Pair" at 5378.02,2616.9 h72
  text "Hole Tolerance" at 6102.35,2616.9 h72
  text "181" at 3775.16,2492.58 h60
  text "8.00mil (0.203mm)" at 4107.16,2492.58 h60
  text "PTH" at 4743.72,2492.58 h60
  text "Round" at 5002.86,2492.58 h60
  text "Top Layer - Bottom Layer" at 5378.02,2492.58 h60
  text "25" at 3775.16,2368.26 h60
  text "11.81mil (0.300mm)" at 4107.16,2368.26 h60
  text "PTH" at 4743.72,2368.26 h60
  text "Round" at 5002.86,2368.26 h60
  text "Top Layer - Bottom Layer" at 5378.02,2368.26 h60
  text "24" at 3775.16,2243.94 h60
  text "16.00mil (0.406mm)" at 4107.16,2243.94 h60
  text "PTH" at 4743.72,2243.94 h60
  text "Round" at 5002.86,2243.94 h60
  text "Top Layer - Bottom Layer" at 5378.02,2243.94 h60
  text "17" at 3775.16,2119.62 h60
  text "40.00mil (1.016mm)" at 4107.16,2119.62 h60
  text "PTH" at 4743.72,2119.62 h60
  text "Round" at 5002.86,2119.62 h60
  text "Top Layer - Bottom Layer" at 5378.02,2119.62 h60
  text "247 Total" at 3775.16,1995.3 h60
  text ".Layer_Name" at -423,-1858.49 h60
M17 Embedded Cavity:
  text ".Layer_Name" at -423,-1858.49 h60
M18 Embedded Assembly:
  text ".Layer_Name" at -423,-1858.49 h60
M19 Embedded Keepout:
  text ".Layer_Name" at -423,-1858.49 h60

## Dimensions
2500,-50 to 0,-50 on M2 Board Dimensions
-50,2200 to -50,0 on M2 Board Dimensions
-1000,-1400 to 0,-1400 on M2 Board Dimensions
